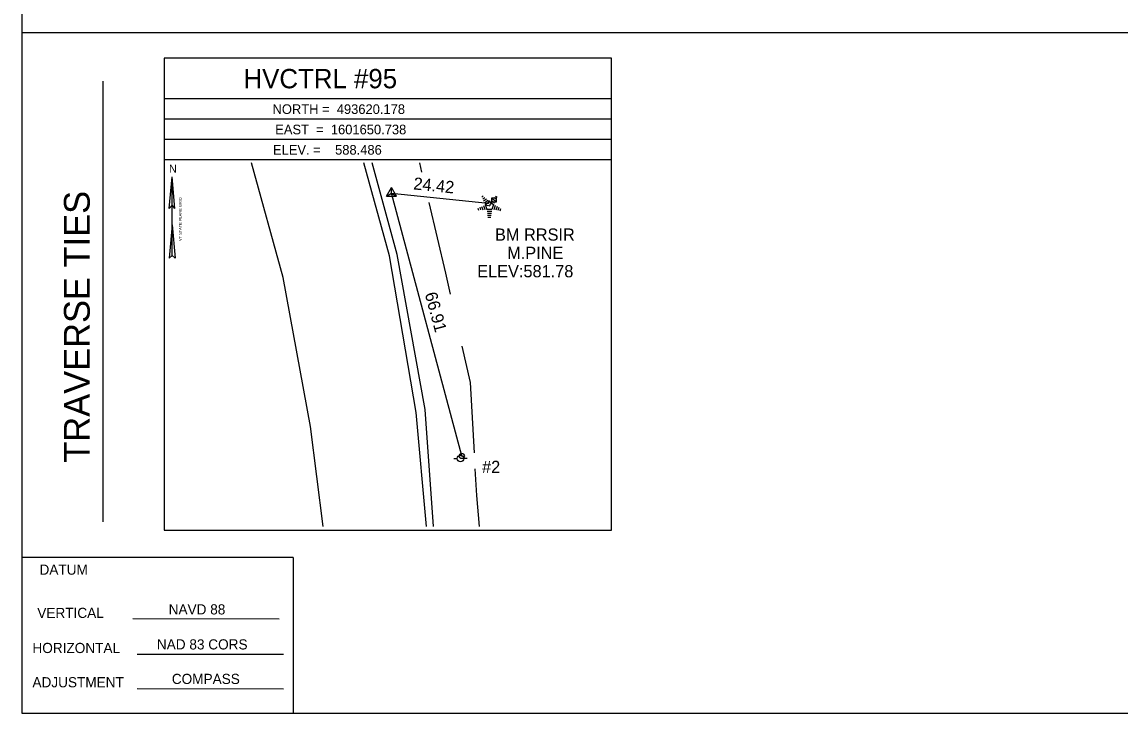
# Model space of a CAD drawing. Extents: x 1598730 to 1599370, y 501440 to 502728.
# Drawn here: x 1598729.5 to 1598999.5, y 501440.2 to 501610.1 of the extents above; entities that cross this region are included whole.
import ezdxf

# ---------------------------------------------------------------- set-up
doc = ezdxf.new("R2010")
doc.units = 0
for name, color, linetype in [('C_C', 7, 'Continuous'), ('CBP', 7, 'Continuous'), ('CPBM', 7, 'Continuous'), ('CPSM', 7, 'Continuous'), ('Default', 7, 'Continuous'), ('LAWA', 7, 'Continuous'), ('LTC', 7, 'Continuous'), ('NBL1', 7, 'Continuous'), ('NBL2', 7, 'Continuous'), ('NNA_P', 7, 'Continuous'), ('PET', 7, 'Continuous'), ('RGR', 7, 'Continuous'), ('U_C', 7, 'Continuous'), ('UP', 7, 'Continuous')]:
    doc.layers.add(name, color=color, linetype=linetype)

msp = doc.modelspace()

# ---------------------------------------------------------------- linework, layer by layer
at = {"layer": 'CBP'}
for centre, radius in [((1598844.17, 501565.56), 0.625), ((1598844.17, 501565.56), 0.0833), ((1598837.7, 501503.41), 0.625), ((1598837.7, 501503.41), 0.0833)]:
    msp.add_circle(centre, radius, dxfattribs=at)
at = {"layer": 'CPBM'}
for p, q in [((1598845.1, 501565.85), (1598845.1, 501566.85)), ((1598845.1, 501566.85), (1598846.1, 501566.85)), ((1598846.1, 501565.85), (1598845.1, 501565.85)), ((1598845.61, 501566.35), (1598845.61, 501566.35)), ((1598845.61, 501566.35), (1598845.61, 501566.35)), ((1598846.1, 501566.85), (1598846.1, 501565.85))]:
    msp.add_line(p, q, dxfattribs=at)
at = {"layer": 'CPSM'}
for p, q in [((1598819.15, 501567.28), (1598820.4, 501569.45)), ((1598819.15, 501567.28), (1598820.4, 501568)), ((1598821.65, 501567.28), (1598820.4, 501569.45)), ((1598820.4, 501568), (1598820.4, 501569.45)), ((1598820.4, 501568), (1598820.4, 501568)), ((1598820.4, 501568), (1598821.65, 501567.28)), ((1598819.15, 501567.28), (1598821.65, 501567.28))]:
    msp.add_line(p, q, dxfattribs=at)
at = {"layer": 'Default'}
for p, q in [((1598837.7, 501503.41), (1598820.4, 501568)), ((1598820.4, 501568), (1598844.17, 501565.56))]:
    msp.add_line(p, q, dxfattribs=at)
at = {"layer": 'LAWA'}
for points in [[(1598827.87, 501573.23), (1598827.34, 501575.46)], [(1598834.89, 501543.21), (1598833.74, 501548.35), (1598829.64, 501565.73)], [(1598840.78, 501504.16), (1598839.8, 501521.46), (1598837.78, 501530.39)], [(1598842.06, 501486.1), (1598841.38, 501493.69), (1598841.01, 501500.28)]]:
    msp.add_lwpolyline(points, dxfattribs=at)
at = {"layer": 'LTC'}
for p, q in [((1598842.55, 501564.79), (1598842.82, 501563.96)), ((1598842.61, 501567.08), (1598842.96, 501567.34)), ((1598842.82, 501566.61), (1598843.35, 501567)), ((1598843.01, 501565.01), (1598843.34, 501563.99)), ((1598843.03, 501566.15), (1598843.73, 501566.66)), ((1598843.24, 501565.68), (1598844.11, 501566.32)), ((1598843.46, 501565.23), (1598844.47, 501565.96)), ((1598843.46, 501565.23), (1598843.85, 501564.03)), ((1598844.47, 501565.96), (1598845.47, 501565.24)), ((1598844.89, 501566.27), (1598845.7, 501565.69)), ((1598845.47, 501565.24), (1598845.08, 501564.03)), ((1598845.26, 501566.62), (1598845.94, 501566.13)), ((1598845.91, 501564.97), (1598845.57, 501563.93)), ((1598845.63, 501566.97), (1598846.18, 501566.57)), ((1598846.01, 501567.32), (1598846.42, 501567.02)), ((1598841.64, 501564.36), (1598841.79, 501563.89)), ((1598842.1, 501564.58), (1598842.31, 501563.92)), ((1598845.08, 501564.03), (1598843.85, 501564.03)), ((1598845.04, 501563.53), (1598843.9, 501563.53)), ((1598844.96, 501563.03), (1598843.97, 501563.03)), ((1598844.87, 501562.53), (1598844.04, 501562.53)), ((1598846.35, 501564.72), (1598846.06, 501563.83)), ((1598846.8, 501564.47), (1598846.56, 501563.74)), ((1598847.24, 501564.22), (1598847.05, 501563.64)), ((1598844.79, 501562.03), (1598844.11, 501562.03))]:
    msp.add_line(p, q, dxfattribs=at)
at = {"layer": 'NBL1'}
msp.add_lwpolyline([(1598729.53, 501440.21), (1599369.53, 501440.21), (1599369.53, 501860.21), (1598729.53, 501860.21)], close=True, dxfattribs=at)
at = {"layer": 'NBL2'}
for p, q in [((1598729.53, 501607.54), (1599369.53, 501607.54)), ((1598749.53, 501487.21), (1598749.53, 501595.54)), ((1598874.53, 501591.19), (1598764.53, 501591.19)), ((1598874.53, 501586.19), (1598764.53, 501586.19)), ((1598874.53, 501581.19), (1598764.53, 501581.19)), ((1598874.53, 501576.19), (1598764.53, 501576.19)), ((1598796.2, 501478.46), (1598729.53, 501478.46)), ((1598796.2, 501478.46), (1598796.2, 501440.21)), ((1598796.2, 501478.46), (1598796.2, 501440.21)), ((1598756.77, 501463.44), (1598792.77, 501463.41)), ((1598757.88, 501454.66), (1598793.88, 501454.66)), ((1598757.88, 501446.23), (1598793.88, 501446.2))]:
    msp.add_line(p, q, dxfattribs=at)
msp.add_lwpolyline([(1598764.53, 501485.19), (1598874.53, 501485.19), (1598874.53, 501601.19), (1598764.53, 501601.19)], close=True, dxfattribs=at)
at = {"layer": 'NNA_P'}
for p, q in [((1598765.77, 501564.29), (1598766.46, 501572.08)), ((1598766.46, 501552.71), (1598766.46, 501572.08)), ((1598767.15, 501564.29), (1598766.46, 501572.08)), ((1598765.77, 501564.29), (1598766.46, 501565.06)), ((1598767.16, 501564.29), (1598766.46, 501565.06)), ((1598766.47, 501560.23), (1598765.74, 501552.07)), ((1598766.46, 501560.23), (1598767.19, 501552.07)), ((1598766.46, 501552.71), (1598765.74, 501552.07)), ((1598766.46, 501552.71), (1598767.19, 501552.07))]:
    msp.add_line(p, q, dxfattribs=at)
at = {"layer": 'PET'}
for points in [[(1598803.57, 501486.1), (1598800.49, 501510.68), (1598793.75, 501547.27), (1598785.95, 501575.46)], [(1598829.04, 501486.1), (1598826.48, 501514.13), (1598819.89, 501552.64), (1598813.59, 501575.46)]]:
    msp.add_lwpolyline(points, dxfattribs=at)
at = {"layer": 'RGR'}
msp.add_lwpolyline([(1598830.7, 501486.1), (1598828.66, 501514.87), (1598821.77, 501552.98), (1598815.61, 501575.46)], dxfattribs=at)
at = {"layer": 'UP'}
for p, q in [((1598835.71, 501502.79), (1598836.54, 501502.79)), ((1598837.37, 501502.79), (1598837.37, 501502.79)), ((1598839.04, 501502.79), (1598838.2, 501502.79)), ((1598838.2, 501502.79), (1598838.2, 501502.79)), ((1598839.04, 501502.79), (1598839.04, 501502.79))]:
    msp.add_line(p, q, dxfattribs=at)
msp.add_circle((1598837.37, 501502.79), 0.833, dxfattribs=at)

# ---------------------------------------------------------------- texts
at = {"layer": 'C_C'}
for s, p in [('BM RRSIR', (1598845.85, 501556.35)), ('M.PINE', (1598848.84, 501551.85)), ('ELEV:581.78', (1598841.47, 501547.35))]:
    msp.add_text(s, height=3, dxfattribs=at).set_placement(p)
at = {"layer": 'Default'}
for s, rotation, p in [('24.42', 354.1375, (1598825.68, 501568.97)), ('66.91', 284.9878, (1598828.57, 501543.28))]:
    msp.add_text(s, height=3, rotation=rotation, dxfattribs=at).set_placement(p)
at = {"layer": 'LTC'}
msp.add_text('.', height=1.04, rotation=270, dxfattribs=at).set_placement((1598844.36, 501564.98))
at = {"layer": 'NBL2'}
for s, height, p in [('     HVCTRL #95    ', 4.75, (1598775.18, 501593.82)), ('NORTH =  493620.178 ', 2.375, (1598791.15, 501587.5)), ('EAST  =  1601650.738', 2.375, (1598791.81, 501582.5)), ('ELEV. =    588.486  ', 2.375, (1598791.26, 501577.5)), ('DATUM', 2.5, (1598733.85, 501474.22)), ('  NAVD 88 ', 2.5, (1598763.75, 501464.45)), ('HORIZONTAL', 2.5, (1598732.11, 501454.96)), ('NAD 83 CORS', 2.5, (1598762.71, 501455.84)), ('ADJUSTMENT', 2.5, (1598732.11, 501446.53)), ('  COMPASS ', 2.5, (1598764.53, 501447.35))]:
    msp.add_text(s, height=height, dxfattribs=at).set_placement(p)
for s, height, rotation, p in [('TRAVERSE TIES', 6.3332, 90, (1598746.2, 501501.76)), ('VERTICAL', 2.5, 0.1439, (1598733.31, 501463.56))]:
    msp.add_text(s, height=height, rotation=rotation, dxfattribs=at).set_placement(p)
at = {"layer": 'NNA_P'}
msp.add_text('N', height=1.97, dxfattribs=at).set_placement((1598765.7, 501573.09))
msp.add_text('VT STATE PLANE GRID', height=0.7, rotation=90.0204, dxfattribs=at).set_placement((1598768.82, 501556.27))
at = {"layer": 'U_C'}
msp.add_text('#2', height=3, dxfattribs=at).set_placement((1598842.67, 501499.23))

doc.saveas('drawing.dxf')
